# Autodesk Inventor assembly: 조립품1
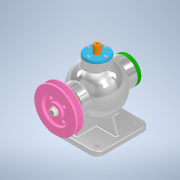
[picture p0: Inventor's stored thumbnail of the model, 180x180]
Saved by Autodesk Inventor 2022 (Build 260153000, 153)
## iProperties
Created: 2024-04
Part Number: 조립품1
Document SubType Name: Assembly
Designer: Admin
Author: Admin
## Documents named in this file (16)
- C:\Users\Admin\Desktop\740406V1010\조립품1.iam
- C:\Users\Admin\Desktop\740406V1010\본체.ipt
- C:\Users\Admin\Desktop\740406V1010\뒤커버.ipt
- C:\Users\Admin\Desktop\740406V1010\앞커버.ipt
- C:\Users\Admin\Desktop\740406V1010\상부커버.ipt
- C:\Users\Admin\Desktop\740406V1010\베어링- 6202.ipt
- KS B 2023 - 6202 - 15 x 35 x 11 - 7.8.ipt
- C:\Users\Admin\Desktop\740406V1010\편심축.ipt
- C:\Users\Admin\Desktop\740406V1010\칼라.ipt
- C:\Users\Admin\Desktop\740406V1010\키 4 x 4 x 12.ipt
- C:\Users\Admin\Desktop\740406V1010\오일실 15 30 7.ipt
- C:\Users\Admin\Desktop\740406V1010\V-벨트풀리.ipt
- C:\Users\Admin\Desktop\740406V1010\너트 M8.ipt
- C:\Users\Admin\Desktop\740406V1010\볼트 M4 x 16.ipt
- C:\Users\Admin\Desktop\740406V1010\볼트 M4 x 12.ipt
- C:\Users\Admin\Desktop\740406V1010\슬라이드.ipt
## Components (15 placed, 4 different names)
1. KS B 2023 - 6202 - 15 x 35 x 11 - 7.8:1
2. KS B 2023 - 6202 - 15 x 35 x 11 - 7.8:2
3. V-벨트풀리:1
4. ISO 4762 M4 x 16:1
5. ISO 4762 M4 x 16:2
6. ISO 4762 M4 x 16:3
7. ISO 4762 M4 x 16:4
8. ISO 4762 M4 x 16:5
9. ISO 4762 M4 x 16:6
10. ISO 4762 M4 x 16:7
11. ISO 4762 M4 x 16:8
12. KS B 1021 - 에 따름 ISO 1207 - 미터 A  M 4 x 12:1
13. KS B 1021 - 에 따름 ISO 1207 - 미터 A  M 4 x 12:2
14. KS B 1021 - 에 따름 ISO 1207 - 미터 A  M 4 x 12:3
15. KS B 1021 - 에 따름 ISO 1207 - 미터 A  M 4 x 12:4
